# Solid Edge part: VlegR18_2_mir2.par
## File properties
Author: Türk
Template: Iso Part.par
Last saved by: Türk
Revision: 2
Application: Solid Edge
Accuracy: 0,990
Username: Türk
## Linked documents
VlegR18_2.par
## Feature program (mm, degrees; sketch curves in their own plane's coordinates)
part copy "CopiedPart_1"
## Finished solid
Body 1: solid body, 154 faces, 385 edges, 214 vertices, 2 internal voids.
  Faces by surface: cylinder 72, torus 31, plane 24, blend 14, cone 8, spun 5
  Edges by curve: circle 176, intersection 113, line 96
Bounding box of the edges (mm; curved faces can reach further): 200.000 x 457.200 x 457.200, from (-100, -228.6, -228.6) to (100, 228.6, 228.6).
Cylindrical faces by radius (mm): R4 x16, R6 x5, R15 x5, R25 x16, R80 x8, R150 x8, R174.2298 x8, R203.6 x2, R216.1 x2, R228.6 x2
Conical faces (half-angle, radius in mm at the cone's reference point): 2.0106 deg R178.4522 x2, 5.4632 deg R201.6202 x2, 54.824 deg R174.2298 x1, 54.824 deg R203.0605 x2, 54.824 deg R203.6 x1
Toroidal faces (ring radius, tube radius in mm): R79 r1 x7, R136.945 r40 x8, R170 r20 x8, R205.6 r2 x2, R214.1 r2 x2, R226.6 r2 x4
Planar faces by outward normal: +x 4, -x 4, oblique 16
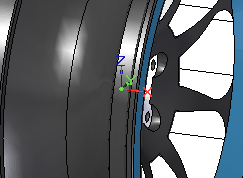
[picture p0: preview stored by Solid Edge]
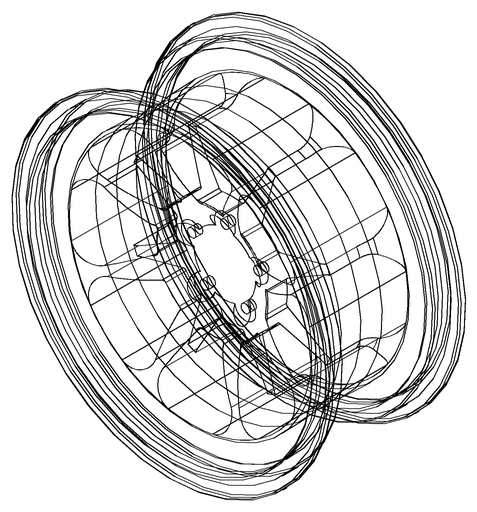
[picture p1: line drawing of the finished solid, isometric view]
